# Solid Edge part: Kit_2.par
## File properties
Sűrűség: 0,000 kg/m^3
Pontosság: 0,990
Author: ahadarics
Last saved by: ahadarics
Revision: 76
Username: ahadarics
Dokumentum tartalom típus: 0
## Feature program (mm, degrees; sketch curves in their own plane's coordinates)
base feature "unnamed BaseFeature 1"
sketch for "Furat_1" plane through (0, 12, 0) normal (0, 1, 0) x-axis (0, 0, 1)
  hole centre (0, 0) bore radius 4.283
hole "Furat_1" nominal diameter 9.728 finite  ThreadDepth = 7.5 mm
chamfer "Letörés_1" setback 0.7
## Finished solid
Body 1: solid body, 19 faces, 22 edges, 6 vertices, 1 internal void.
  Faces by surface: cylinder 7, plane 7, cone 5
  Edges by curve: circle 15, line 4, spline 2, intersection 1
Bounding box of the edges (mm): 27.000 x 25.500 x 23.000, from (-13.5, -13.5, -15.25) to (13.5, 12, 7.75).
Cylindrical faces by radius (mm): R0.85 x1, R4.28 x1, R4.283 x1, R8.95 x1, R10 x1, R11.1 x1, R13.5 x1
Conical faces (half-angle, radius in mm at the cone's reference point): 30 deg R9.9134 x1, 45 deg R4.983 x1, 45 deg R9.475 x1, 45 deg R13.25 x1, 59 deg R2.1415 x1
Planar faces by outward normal: +y 2, +z 1, -y 1, -z 3
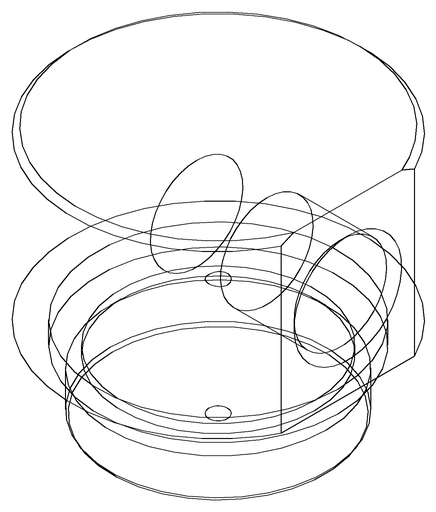
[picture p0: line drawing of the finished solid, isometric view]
